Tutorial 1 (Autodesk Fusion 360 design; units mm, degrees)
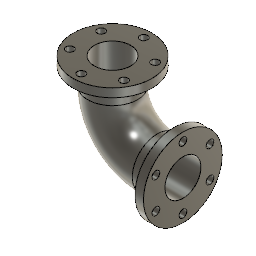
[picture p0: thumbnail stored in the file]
sketch "Sketch1" plane through (0, 0, 0) normal (0, 1, 0) x axis (1, 0, 0)
  line L1 (0, 100) -> (0, 0)
  line L2 (360, 360) -> (260, 360)
  arc A1 centre (260, 100) radius 260 clockwise from (0, 100) to (260, 360)
  point P1 (0, 0)
  point P2 (0, 0)
  point P3 (0, 100)
  point P4 (260, 360)
  point P6 (360, 360)
  coincident P1 P2
  vertical L1
  tangent L1 A1
  perpendicular L1 L2
  tangent A1 L2
  dimension "d1" distance P2 P3 = 100
  dimension "d2" distance P4 P6 = 100
  dimension "d3" radius A1 = 260
sketch "Sketch2" plane through (0, 0, 0) normal (0, 0, 1) x axis (1, 0, 0)
  circle C1 centre (0, 0) radius 145
  circle C2 centre (0, 0) radius 105
  point P1 (0, 0)
  point P2 (0, 0)
  coincident P1 P2
  concentric C1 C2
  dimension "d4" diameter C1 = 290
  dimension "d5" diameter C2 = 210
sweep "Sweep1" sketch "Sketch2" + "Sketch4" TwistAngle 0 TaperAngle 0
sketch "Sketch3" plane through (0, 0, 0) normal (0, 0, 1) x axis (-1, 0, 0)
  circle C1 centre (0, 0) radius 105
  circle C2 centre (0, 0) radius 145
  circle C3 centre (0, 0) radius 230
  point P1 (0, 0)
  point P3 (0, 0)
  coincident P1 P3
  dimension "d12" diameter C3 = 460
extrude "Extrude1" add sketch "Sketch3" along normal blind 50
sketch "Sketch4" plane through (0, 0, 50) normal (0, 0, 1) x axis (-1, 0, 0)
  circle C1 centre (0, 0) radius 105
  circle C2 centre (0, 0) radius 230
  circle C3 centre (0, -182) radius 22.5
  point P1 (0, 0)
  point P3 (0, -182)
  vertical P1 P3
  dimension "d15" diameter C3 = 45
  dimension "d16" distance P1 P3 = 182
extrude "Extrude3" cut sketch "Sketch4" profile of C3 to an object
circular_pattern "C-Pattern1" sketch "Sketch4" TotalAngle 360
sketch "Sketch5" plane through (360, 0, 0) normal (1, 0, 0) x axis (0, 1, 0)
  circle C1 centre (0, -360) radius 105
  circle C2 centre (0, -360) radius 145
  circle C3 centre (0, -360) radius 230
  concentric C1 C3
  dimension "d23" diameter C3 = 460
extrude "Extrude4" add sketch "Sketch5" along normal blind 50
sketch "Sketch6" plane through (410, 0, 0) normal (1, 0, 0) x axis (0, 1, 0)
  circle C1 centre (0, -360) radius 105
  circle C2 centre (0, -360) radius 230
  circle C3 centre (0, -542) radius 22.5
  point P1 (0, 0)
  point P3 (0, -542)
  point P2 (0, -360)
  vertical P1 P3
  dimension "d26" diameter C3 = 45
  dimension "d27" distance P2 P3 = 182
extrude "Extrude5" cut sketch "Sketch6" profile of C3 to an object
circular_pattern "C-Pattern2" sketch "Sketch4" TotalAngle 360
